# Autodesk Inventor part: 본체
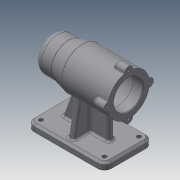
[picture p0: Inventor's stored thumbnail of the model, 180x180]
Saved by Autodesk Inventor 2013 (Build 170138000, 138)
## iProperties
Created: 2019-07
Part Number: 본체
Material: 일반
Document SubType Name: Modeling
Designer: a
Density: 1 g/cm^3
Author: a
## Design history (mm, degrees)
sketch "스케치1"
  geometry: L1 (-56, 0)-(56, 0); L2 (-56, 0)-(-56, 25); L3 (-56, 25)-(-31, 25); L4 (-31, 25)-(-11, 30); L5 (-11, 30)-(56, 30); L6 (56, 30)-(56, 0); L7 (-50, 0)-(-50, 10.5); L8 (-50, 10.5)-(-47, 10.5); L9 (-47, 10.5)-(-47, 16); L10 (-47, 16)-(-43, 16); L11 (-43, 16)-(-43, 17.5); L12 (-43, 17.5)-(-25, 17.5); L13 (-25, 17.5)-(-25, 21); L14 (-25, 21)-(-13, 21); L15 (-13, 21)-(-13, 24); L16 (-13, 24)-(41, 24); L17 (41, 24)-(41, 21); L18 (41, 21)-(56, 21); 2 further points
  constraints: 36 end point, 11 parallel, 5 perpendicular, 2 point on line, 1 coincident, 1 horizontal, 1 midpoint
  dimensions: "d0" = 112 distance of L1.start L1.end; "d1" = 42 diameter of L18 L1; "d2" = 48 diameter of L16 L1; "d3" = 42 diameter of L14 L1; "d4" = 35 diameter of L12 L1; "d5" = 32 diameter of L10 L1; "d6" = 21 diameter of L8 L1; "d7" = 50 diameter of L3 L1; "d8" = 60 diameter of L5 L1; "d9" = 15 distance of L17.end L18.end; "d10" = 54 distance of L15.end L16.end; "d11" = 12 distance of L13.end L14.end; "d12" = 18 distance of L11.end L12.end; "d13" = 4 distance of L9.end L10.end; "d14" = 3 distance of L7.end L8.end; "d15" = 25 distance of L2.end L3.end; "d16" = 20 horizontal distance of L3.end L4.end
revolve "회전1" sketch "스케치1" stored, may be unused: angle "d17" = 90 deg
sketch "스케치2"
  geometry: C1 r 21 at (0, 0) reference; C2 r 6 at (0, 30); C3 r 6 at (30, 0); C4 r 6 at (0, -30); C5 r 6 at (-30, 0); A1 r 30 centre (0, 0) between (0, 30) and (30, 0) reference
  constraints: 4 centre point, 4 point on circle, 2 horizontal alignment, 2 vertical alignment
  dimensions: "d18" = 12 diameter of C2; "d19" = 12 diameter of C3; "d20" = 12 diameter of C4; "d21" = 12 diameter of C5
extrude "돌출1" join sketch "스케치2" distance "d22" = 16; taper "d23" = 0 deg
sketch "스케치3"
  geometry: A1 r 6 centre (-30, -30) between (-35.97, -29.4) and (-24.03, -29.4) reference; A2 r 6 centre (0, 0) between (-0.6, -5.97) and (-0.6, 5.97) reference; A3 r 6 centre (-30, 30) between (-24.03, 29.4) and (-35.97, 29.4) reference; A4 r 6 centre (-60, 0) between (-59.4, 5.97) and (-59.4, -5.97) reference; 4 further points
  constraints: 4 coincident
hole "구멍1" sketch "스케치3" at (-30, 30), (0, 0), (-30, -30), (-60, 0) diameter "d24" = 3.242; stored, may be unused: countersink angle "d28" = 90 deg, drill point angle "d30" = 118 deg; dims "d25" = 8, "d26" = 4, "d27" = 2, "d29" = 11
node "작업 평면1"
sketch "스케치4"
  geometry: L1 (56, 35)-(-56, 35); L2 (-56, 35)-(-56, -35); L3 (-56, -35)-(56, -35); L4 (56, -35)-(56, 35); L5 (56, 35)-(-56, -35); L6 (-56, 35)-(56, -35); 1 further point
  constraints: 12 end point, 2 midpoint, 2 parallel, 1 horizontal, 1 perpendicular
  dimensions: "d32" = 112 distance of L3.end L2.end; "d33" = 70 distance of L2.end L1.end
extrude "돌출2" join sketch "스케치4" distance "d34" = 10; taper "d35" = 0 deg
fillet "모깎기1" dims "d36" = 10
chamfer "모따기1" distance "d37" = 3; stored, may be unused: second distance "d38" = 2, angle "d39" = 45 deg
sketch "스케치5"
  geometry: A1 r 7 centre (46, -25) between (46, -32) and (53, -25) reference; A2 r 7 centre (46, 25) between (53, 25) and (46, 32) reference; A3 r 7 centre (-46, 25) between (-46, 32) and (-53, 25) reference; A4 r 7 centre (-46, -25) between (-53, -25) and (-46, -32) reference; 5 further points
  constraints: 4 coincident
hole "구멍2" sketch "스케치5" at (-46, 25), (46, 25), (46, -25), (-46, -25) diameter "d40" = 6; stored, may be unused: countersink angle "d44" = 90 deg, drill point angle "d46" = 118 deg; dims "d41" = 8, "d42" = 4, "d43" = 2, "d45" = 11
sketch "스케치9"
  geometry: L1 (-70, 25)-(-70, -25) reference; L2 (-70, -22)-(-70, -28) reference; L3 (-70, -25)-(-70, -32) reference; L4 (-70, 32)-(-70, 25) reference; L5 (-80, 35)-(-73, 35) reference; L6 (-73, -35)-(-80, -35) reference; L7 (-22.666, -19.654)-(-70, -28); L8 (-70, 28)-(-22.666, 19.654); L9 (-22.666, 19.654)-(-30, 0); L10 (-22.666, -19.654)-(-30, 0); L11 (-70, 28)-(-70, -28); A1 r 30 centre (0, 0) between (-22.666, -19.654) and (-22.666, 19.654) reference; 1 further point
  constraints: 10 end point, 3 point on circle, 2 point on line, 1 horizontal alignment, 1 perpendicular
  dimensions: "d77" = 100 deg angle of L1 L7; "d79" = 100 deg angle of L1 L8; "d80" = 7 distance from line of L5 L8.start; "d81" = 7 distance from line of L7.end L6
extrude "돌출5" join sketch "스케치9" stored distance "d82" = 8; taper "d83" = 0 deg
sketch "스케치10"
  geometry: L1 (-31, -25)-(-11, -30) reference; L2 (-56, -25)-(-31, -25) reference; L3 (-46, -70)-(46, -70) reference; L4 (-53, -70)-(-46, -70) reference; L5 (46, -70)-(53, -70) reference; L6 (-36, -70)-(-20.57, -27.607); L7 (31, -27.607)-(31, -70); L8 (-4, -22.666)-(-4, -70) reference; L9 (4, -70)-(4, -22.666) reference; L10 (-36, -70)-(-4, -70); L11 (-4, -70)-(-4, -30); L12 (4, -70)-(4, -27.607); L13 (4, -70)-(31, -70); L14 (-56, -80)-(-56, -73) reference; L15 (56, -73)-(56, -80) reference; L16 (-20.57, -27.607)-(-4, -30); L17 (4, -27.607)-(31, -27.607); 1 further point
  constraints: 16 end point, 5 point on line, 3 collinear, 2 perpendicular
  dimensions: "d84" = 110 deg angle of L3 L6; "d85" = 20 distance from line of L14 L6.start; "d86" = 25 distance from line of L15 L7.end; "d98" = 42.39259 distance of L7.start L7.end
extrude "돌출6" join sketch "스케치10" stored distance "d87" = 8; taper "d88" = 0 deg
fillet "모깎기3" dims "d89" = 3
fillet "모깎기4" dims "d90" = 3
fillet "모깎기5" dims "d91" = 0.3
chamfer "모따기2" distance "d92" = 1; stored, may be unused: second distance "d93" = 2, angle "d94" = 45 deg
fillet "모깎기6" dims "d95" = 3
fillet "모깎기7" dims "d96" = 1
fillet "모깎기8" dims "d97" = 10
fillet "모깎기9" dims "d99" = 1
node "솔리드1"
